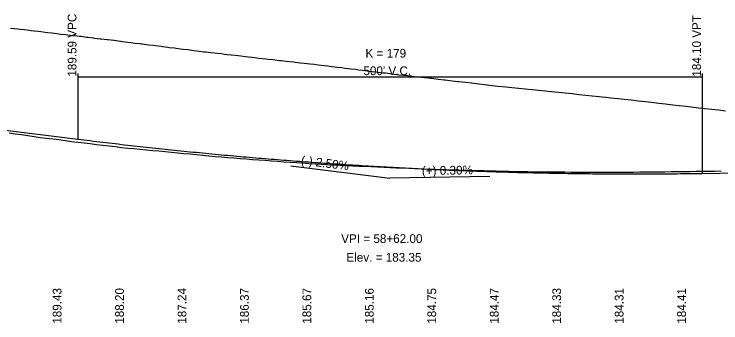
# Model space of a CAD drawing. Extents: x 1838386 to 1955906, y 719739 to 834437.
# Drawn here: x 1882224 to 1882790, y 820601 to 820848 of the extents above; entities that cross this region are included whole.
import ezdxf

# ---------------------------------------------------------------- set-up
doc = ezdxf.new("R2010")
doc.units = 0
for name, color, linetype in [('RD_DDB_GradeTX', 7, 'Continuous'), ('RD_DDB_Profile_EX', 7, 'Continuous'), ('RD_DDB_Profile_Lbl', 7, 'Continuous'), ('RD_DDB_Profile_PR', 7, 'Continuous'), ('RD_DDB_StripGrade', 7, 'Continuous'), ('RD_DDB_VCLbl', 7, 'Continuous'), ('RD_Sketch1', 7, 'Continuous')]:
    doc.layers.add(name, color=color, linetype=linetype)

msp = doc.modelspace()

# ---------------------------------------------------------------- linework, layer by layer
at = {"layer": 'RD_DDB_GradeTX'}
for p in [(1882445.7, 820726.77), (1882605.07, 820718.06)]:
    msp.add_line(p, (1882525.08, 820716.86), dxfattribs=at)
at = {"layer": 'RD_DDB_Profile_EX'}
for points in [[(1882220.15, 820753.1), (1882225.15, 820752.41), (1882230.15, 820751.66), (1882235.15, 820750.89), (1882240.15, 820750.16), (1882245.15, 820749.47), (1882250.15, 820748.87), (1882255.15, 820748.27), (1882260.15, 820747.66), (1882265.15, 820746.98), (1882270.15, 820746.26), (1882275.15, 820745.58), (1882280.15, 820745.01), (1882285.15, 820744.48), (1882290.15, 820743.84), (1882295.15, 820743.26), (1882300.15, 820742.68), (1882305.15, 820742.08), (1882310.15, 820741.45), (1882315.15, 820740.91), (1882320.15, 820740.42), (1882325.15, 820739.96), (1882330.15, 820739.51), (1882335.15, 820739.05), (1882340.15, 820738.57), (1882345.15, 820738.07), (1882350.15, 820737.58), (1882355.15, 820737.1), (1882360.15, 820736.61), (1882365.15, 820736.14), (1882370.15, 820735.7), (1882375.15, 820735.22), (1882380.15, 820734.72), (1882385.15, 820734.23), (1882390.15, 820733.82)], [(1882390.15, 820733.82), (1882395.15, 820733.43), (1882400.15, 820733), (1882405.15, 820732.56), (1882410.15, 820732.17), (1882415.15, 820731.82), (1882420.15, 820731.5), (1882425.15, 820731.14), (1882430.15, 820730.75), (1882435.15, 820730.36), (1882440.15, 820729.99), (1882445.15, 820729.64), (1882450.15, 820729.3), (1882455.15, 820728.95), (1882460.15, 820728.65), (1882465.15, 820728.33), (1882470.15, 820728.03), (1882475.15, 820727.73), (1882480.15, 820727.43), (1882485.15, 820727.12), (1882490.15, 820726.82), (1882495.15, 820726.59), (1882500.15, 820726.41), (1882505.15, 820726.27), (1882510.15, 820726.06), (1882515.15, 820725.84), (1882520.15, 820725.63), (1882525.15, 820725.38), (1882530.15, 820725.15), (1882535.15, 820724.92), (1882540.15, 820724.72), (1882545.15, 820724.53), (1882550.15, 820724.31), (1882555.15, 820724.11), (1882560.15, 820723.95), (1882565.15, 820723.8), (1882570.15, 820723.65), (1882575.15, 820723.49), (1882580.15, 820723.34), (1882585.15, 820723.18), (1882590.15, 820723.03), (1882595.15, 820722.91), (1882600.15, 820722.79), (1882605.15, 820722.68), (1882610.15, 820722.56), (1882615.15, 820722.45), (1882620.15, 820722.33), (1882625.15, 820722.23), (1882630.15, 820722.11), (1882635.15, 820721.99), (1882640.15, 820721.91), (1882645.15, 820721.88), (1882650.15, 820721.86), (1882655.15, 820721.85), (1882660.15, 820721.81), (1882665.15, 820721.74), (1882670.15, 820721.68), (1882675.15, 820721.67), (1882680.15, 820721.65), (1882685.15, 820721.63), (1882690.15, 820721.6), (1882695.15, 820721.61), (1882700.15, 820721.61), (1882705.15, 820721.62), (1882710.15, 820721.64), (1882715.15, 820721.67), (1882720.15, 820721.7), (1882725.15, 820721.72), (1882730.15, 820721.79), (1882735.15, 820721.85), (1882740.15, 820721.9), (1882745.15, 820721.97), (1882750.15, 820722.03), (1882755.15, 820722.09), (1882760.15, 820722.16), (1882765.15, 820722.23), (1882770.15, 820722.3), (1882775.15, 820722.35), (1882780.15, 820722.43), (1882785.15, 820722.51), (1882790.15, 820722.55)]]:
    msp.add_lwpolyline(points, dxfattribs=at)
at = {"layer": 'RD_DDB_Profile_PR'}
for p, q in [((1881558.08, 820837.6), (1882275.08, 820748.07)), ((1882775.08, 820720.61), (1883530.2, 820731.93))]:
    msp.add_line(p, q, dxfattribs=at)
msp.add_spline([(1882275.08, 820748.07), (1882285.08, 820746.84), (1882295.08, 820745.63), (1882305.08, 820744.45), (1882315.08, 820743.3), (1882325.08, 820742.18), (1882335.08, 820741.08), (1882345.08, 820740.02), (1882355.08, 820738.98), (1882365.08, 820737.97), (1882375.08, 820736.98), (1882385.08, 820736.03), (1882395.08, 820735.1), (1882405.08, 820734.2), (1882415.08, 820733.33), (1882425.08, 820732.49), (1882435.08, 820731.67), (1882445.08, 820730.89), (1882455.08, 820730.13), (1882465.08, 820729.4), (1882475.08, 820728.69), (1882485.08, 820728.02), (1882495.08, 820727.37), (1882505.08, 820726.75), (1882515.08, 820726.16), (1882525.08, 820725.6), (1882535.08, 820725.06), (1882545.08, 820724.55), (1882555.08, 820724.08), (1882565.08, 820723.62), (1882575.08, 820723.2), (1882585.08, 820722.8), (1882595.08, 820722.44), (1882605.08, 820722.1), (1882615.08, 820721.79), (1882625.08, 820721.5), (1882635.08, 820721.25), (1882645.08, 820721.02), (1882655.08, 820720.82), (1882665.08, 820720.65), (1882675.08, 820720.5), (1882685.08, 820720.39), (1882695.08, 820720.3), (1882705.08, 820720.24), (1882715.08, 820720.21), (1882725.08, 820720.21), (1882735.08, 820720.23), (1882745.08, 820720.28), (1882755.08, 820720.36), (1882765.08, 820720.47), (1882775.08, 820720.61)], degree=3, dxfattribs=at)
at = {"layer": 'RD_DDB_VCLbl'}
for p, q in [((1882275.08, 820800.57), (1882275.08, 820748.07)), ((1882275.08, 820798.07), (1882775.08, 820798.07)), ((1882775.08, 820800.57), (1882775.08, 820720.61))]:
    msp.add_line(p, q, dxfattribs=at)
at = {"layer": 'RD_Sketch1'}
msp.add_lwpolyline([(1882221.33, 820837), (1882224.33, 820836.68), (1882226.87, 820836.38), (1882229.17, 820836.11), (1882232.39, 820835.75), (1882234.62, 820835.51), (1882237.92, 820835.13), (1882240.2, 820834.86), (1882243.46, 820834.45), (1882245.65, 820834.16), (1882248.97, 820833.77), (1882250.92, 820833.54), (1882254.48, 820833.14), (1882256.58, 820832.9), (1882260.02, 820832.48), (1882261.71, 820832.27), (1882265.55, 820831.79), (1882267.28, 820831.57), (1882271.05, 820831.14), (1882272.4, 820830.99), (1882276.56, 820830.56), (1882277.77, 820830.44), (1882282.14, 820829.81), (1882283.18, 820829.66), (1882287.64, 820829.11), (1882288.4, 820829.01), (1882293.14, 820828.5), (1882293.86, 820828.42), (1882298.68, 820827.82), (1882299.08, 820827.77), (1882304.14, 820827.22), (1882304.21, 820827.21), (1882307.5, 820826.79), (1882309.77, 820826.43), (1882310.84, 820826.26), (1882315.25, 820825.72), (1882317.63, 820825.43), (1882320.77, 820825.05), (1882324.6, 820824.6), (1882326.29, 820824.41), (1882327, 820824.32), (1882330.19, 820823.9), (1882331.83, 820823.69), (1882335.51, 820823.21), (1882337.35, 820822.97), (1882341.83, 820822.41), (1882342.87, 820822.28), (1882347.3, 820821.72), (1882348.4, 820821.58), (1882352.5, 820821.06), (1882353.91, 820820.9), (1882357.49, 820820.48), (1882359.45, 820820.22), (1882363.24, 820819.73), (1882364.99, 820819.48), (1882368.18, 820819.02), (1882370.5, 820818.71), (1882374.12, 820818.22), (1882375.98, 820818.04), (1882377.7, 820817.87), (1882379.67, 820817.68), (1882381.51, 820817.47), (1882384.48, 820817.14), (1882387.04, 820816.86), (1882390.09, 820816.52), (1882392.57, 820816.24), (1882395, 820815.95), (1882398.09, 820815.59), (1882401.08, 820815.24), (1882403.61, 820814.95), (1882405.74, 820814.71), (1882409.15, 820814.28), (1882411.72, 820813.95), (1882414.65, 820813.63), (1882416.75, 820813.4), (1882420.17, 820813.04), (1882422.73, 820812.76), (1882425.72, 820812.4), (1882427.5, 820812.18), (1882431.24, 820811.71), (1882433.28, 820811.45), (1882436.74, 820811.1), (1882437.99, 820810.97), (1882442.28, 820810.48), (1882444.61, 820810.21), (1882447.79, 820809.87), (1882449.29, 820809.7), (1882453.32, 820809.26), (1882456.5, 820808.9), (1882458.84, 820808.65), (1882461.32, 820808.37), (1882464.38, 820807.99), (1882467.7, 820807.58), (1882469.89, 820807.32), (1882472.42, 820807.03), (1882475.43, 820806.65), (1882478.67, 820806.24), (1882480.94, 820805.97), (1882483.21, 820805.71), (1882486.46, 820805.33), (1882489.06, 820805.02), (1882491.99, 820804.68), (1882493.69, 820804.48), (1882497.53, 820803.98), (1882499.93, 820803.66), (1882503.04, 820803.28), (1882504.89, 820803.05), (1882508.58, 820802.54), (1882510.72, 820802.24), (1882514.08, 820801.86), (1882515.37, 820801.71), (1882519.59, 820801.26), (1882521.56, 820801.05), (1882525.13, 820800.62), (1882526.25, 820800.48), (1882530.67, 820799.88), (1882532.12, 820799.68), (1882536.16, 820799.25), (1882536.93, 820799.17), (1882541.69, 820798.63), (1882542.34, 820798.55), (1882546.79, 820798.04), (1882547.21, 820797.99), (1882552.74, 820797.38), (1882553.39, 820797.31), (1882557.69, 820796.89), (1882558.27, 820796.82), (1882563.79, 820796.16), (1882563.85, 820796.16), (1882568.45, 820795.63), (1882569.32, 820795.53), (1882574.84, 820794.87), (1882574.92, 820794.86), (1882579.75, 820794.3), (1882580.35, 820794.23), (1882585.81, 820793.61), (1882585.87, 820793.61), (1882590.36, 820793.13), (1882596.29, 820792.37), (1882600.82, 820791.86), (1882607, 820791.11), (1882611.79, 820790.54), (1882617.81, 820789.95), (1882622.75, 820789.43), (1882628.36, 820788.83), (1882633.31, 820788.27), (1882638.98, 820787.73), (1882643.86, 820787.27), (1882649.58, 820786.68), (1882654.27, 820786.2), (1882660.16, 820785.55), (1882665.25, 820785.04), (1882671.11, 820784.49), (1882676.43, 820783.93), (1882681.91, 820783.37), (1882686.9, 820782.81), (1882692.54, 820782.12), (1882695.07, 820781.85), (1882697.85, 820781.55), (1882701.98, 820781.16), (1882707.53, 820780.68), (1882712.97, 820780.14), (1882718.41, 820779.48), (1882723.95, 820778.75), (1882729.76, 820778.09), (1882734.62, 820777.56), (1882740.3, 820776.91), (1882745.71, 820776.27), (1882751.57, 820775.63), (1882756.71, 820775.1), (1882762.29, 820774.45), (1882766.28, 820773.94), (1882772.16, 820773.21), (1882777.13, 820772.63), (1882782.76, 820772), (1882788.01, 820771.43), (1882793.77, 820770.7)], dxfattribs=at)
msp.add_lwpolyline([(1882221.33, 820837), (1882224.33, 820836.68), (1882226.87, 820836.38), (1882229.17, 820836.11), (1882232.39, 820835.75), (1882234.62, 820835.51), (1882237.92, 820835.13), (1882240.2, 820834.86), (1882243.46, 820834.45), (1882245.65, 820834.16), (1882248.97, 820833.77), (1882250.92, 820833.54), (1882254.48, 820833.14), (1882256.58, 820832.9), (1882260.02, 820832.48), (1882261.71, 820832.27), (1882265.55, 820831.79), (1882267.28, 820831.57), (1882271.05, 820831.14), (1882272.4, 820830.99), (1882276.56, 820830.56), (1882277.77, 820830.44), (1882282.14, 820829.81), (1882283.18, 820829.66), (1882287.64, 820829.11), (1882288.4, 820829.01), (1882293.14, 820828.5), (1882293.86, 820828.42), (1882298.68, 820827.82), (1882299.08, 820827.77), (1882304.14, 820827.22), (1882304.21, 820827.21), (1882307.5, 820826.79), (1882309.77, 820826.43), (1882310.84, 820826.26), (1882315.25, 820825.72), (1882317.63, 820825.43), (1882320.77, 820825.05), (1882324.6, 820824.6), (1882326.29, 820824.41), (1882327, 820824.32), (1882330.19, 820823.9), (1882331.83, 820823.69), (1882335.51, 820823.21), (1882337.35, 820822.97), (1882341.83, 820822.41), (1882342.87, 820822.28), (1882347.3, 820821.72), (1882348.4, 820821.58), (1882352.5, 820821.06), (1882353.91, 820820.9), (1882357.49, 820820.48), (1882359.45, 820820.22), (1882363.24, 820819.73), (1882364.99, 820819.48), (1882368.18, 820819.02), (1882370.5, 820818.71), (1882374.12, 820818.22), (1882375.98, 820818.04), (1882377.7, 820817.87), (1882379.67, 820817.68), (1882381.51, 820817.47), (1882384.48, 820817.14), (1882387.04, 820816.86), (1882390.09, 820816.52), (1882392.57, 820816.24), (1882395, 820815.95), (1882398.09, 820815.59), (1882401.08, 820815.24), (1882403.61, 820814.95), (1882405.74, 820814.71), (1882409.15, 820814.28), (1882411.72, 820813.95), (1882414.65, 820813.63), (1882416.75, 820813.4), (1882420.17, 820813.04), (1882422.73, 820812.76), (1882425.72, 820812.4), (1882427.5, 820812.18), (1882431.24, 820811.71), (1882433.28, 820811.45), (1882436.74, 820811.1), (1882437.99, 820810.97), (1882442.28, 820810.48), (1882444.61, 820810.21), (1882447.79, 820809.87), (1882449.29, 820809.7), (1882453.32, 820809.26), (1882456.5, 820808.9), (1882458.84, 820808.65), (1882461.32, 820808.37), (1882464.38, 820807.99), (1882467.7, 820807.58), (1882469.89, 820807.32), (1882472.42, 820807.03), (1882475.43, 820806.65), (1882478.67, 820806.24), (1882480.94, 820805.97), (1882483.21, 820805.71), (1882486.46, 820805.33), (1882489.06, 820805.02), (1882491.99, 820804.68), (1882493.69, 820804.48), (1882497.53, 820803.98), (1882499.93, 820803.66), (1882503.04, 820803.28), (1882504.89, 820803.05), (1882508.58, 820802.54), (1882510.72, 820802.24), (1882514.08, 820801.86), (1882515.37, 820801.71), (1882519.59, 820801.26), (1882521.56, 820801.05), (1882525.13, 820800.62), (1882526.25, 820800.48), (1882530.67, 820799.88), (1882532.12, 820799.68), (1882536.16, 820799.25), (1882536.93, 820799.17), (1882541.69, 820798.63), (1882542.34, 820798.55), (1882546.79, 820798.04), (1882547.21, 820797.99), (1882552.74, 820797.38), (1882553.39, 820797.31), (1882557.69, 820796.89), (1882558.27, 820796.82), (1882563.79, 820796.16), (1882563.85, 820796.16), (1882568.45, 820795.63), (1882569.32, 820795.53), (1882574.84, 820794.87), (1882574.92, 820794.86), (1882579.75, 820794.3), (1882580.35, 820794.23), (1882585.81, 820793.61), (1882585.87, 820793.61), (1882590.36, 820793.13), (1882596.29, 820792.37), (1882600.82, 820791.86), (1882607, 820791.11), (1882611.79, 820790.54), (1882617.81, 820789.95), (1882622.75, 820789.43), (1882628.36, 820788.83), (1882633.31, 820788.27), (1882638.98, 820787.73), (1882643.86, 820787.27), (1882649.58, 820786.68), (1882654.27, 820786.2), (1882660.16, 820785.55), (1882665.25, 820785.04), (1882671.11, 820784.49), (1882676.43, 820783.93), (1882681.91, 820783.37), (1882686.9, 820782.81), (1882692.54, 820782.12), (1882695.07, 820781.85), (1882697.85, 820781.55), (1882701.98, 820781.16), (1882707.53, 820780.68), (1882712.97, 820780.14), (1882718.41, 820779.48), (1882723.95, 820778.75), (1882729.76, 820778.09), (1882734.62, 820777.56), (1882740.3, 820776.91), (1882745.71, 820776.27), (1882751.57, 820775.63), (1882756.71, 820775.1), (1882762.29, 820774.45), (1882766.28, 820773.94), (1882772.16, 820773.21), (1882777.13, 820772.63), (1882782.76, 820772), (1882788.01, 820771.43), (1882793.77, 820770.7)], dxfattribs=at)
msp.add_lwpolyline([(1882221.33, 820837), (1882224.33, 820836.68), (1882226.87, 820836.38), (1882229.17, 820836.11), (1882232.39, 820835.75), (1882234.62, 820835.51), (1882237.92, 820835.13), (1882240.2, 820834.86), (1882243.46, 820834.45), (1882245.65, 820834.16), (1882248.97, 820833.77), (1882250.92, 820833.54), (1882254.48, 820833.14), (1882256.58, 820832.9), (1882260.02, 820832.48), (1882261.71, 820832.27), (1882265.55, 820831.79), (1882267.28, 820831.57), (1882271.05, 820831.14), (1882272.4, 820830.99), (1882276.56, 820830.56), (1882277.77, 820830.44), (1882282.14, 820829.81), (1882283.18, 820829.66), (1882287.64, 820829.11), (1882288.4, 820829.01), (1882293.14, 820828.5), (1882293.86, 820828.42), (1882298.68, 820827.82), (1882299.08, 820827.77), (1882304.14, 820827.22), (1882304.21, 820827.21), (1882307.5, 820826.79), (1882309.77, 820826.43), (1882310.84, 820826.26), (1882315.25, 820825.72), (1882317.63, 820825.43), (1882320.77, 820825.05), (1882324.6, 820824.6), (1882326.29, 820824.41), (1882327, 820824.32), (1882330.19, 820823.9), (1882331.83, 820823.69), (1882335.51, 820823.21), (1882337.35, 820822.97), (1882341.83, 820822.41), (1882342.87, 820822.28), (1882347.3, 820821.72), (1882348.4, 820821.58), (1882352.5, 820821.06), (1882353.91, 820820.9), (1882357.49, 820820.48), (1882359.45, 820820.22), (1882363.24, 820819.73), (1882364.99, 820819.48), (1882368.18, 820819.02), (1882370.5, 820818.71), (1882374.12, 820818.22), (1882375.98, 820818.04), (1882377.7, 820817.87), (1882379.67, 820817.68), (1882381.51, 820817.47), (1882384.48, 820817.14), (1882387.04, 820816.86), (1882390.09, 820816.52), (1882392.57, 820816.24), (1882395, 820815.95), (1882398.09, 820815.59), (1882401.08, 820815.24), (1882403.61, 820814.95), (1882405.74, 820814.71), (1882409.15, 820814.28), (1882411.72, 820813.95), (1882414.65, 820813.63), (1882416.75, 820813.4), (1882420.17, 820813.04), (1882422.73, 820812.76), (1882425.72, 820812.4), (1882427.5, 820812.18), (1882431.24, 820811.71), (1882433.28, 820811.45), (1882436.74, 820811.1), (1882437.99, 820810.97), (1882442.28, 820810.48), (1882444.61, 820810.21), (1882447.79, 820809.87), (1882449.29, 820809.7), (1882453.32, 820809.26), (1882456.5, 820808.9), (1882458.84, 820808.65), (1882461.32, 820808.37), (1882464.38, 820807.99), (1882467.7, 820807.58), (1882469.89, 820807.32), (1882472.42, 820807.03), (1882475.43, 820806.65), (1882478.67, 820806.24), (1882480.94, 820805.97), (1882483.21, 820805.71), (1882486.46, 820805.33), (1882489.06, 820805.02), (1882491.99, 820804.68), (1882493.69, 820804.48), (1882497.53, 820803.98), (1882499.93, 820803.66), (1882503.04, 820803.28), (1882504.89, 820803.05), (1882508.58, 820802.54), (1882510.72, 820802.24), (1882514.08, 820801.86), (1882515.37, 820801.71), (1882519.59, 820801.26), (1882521.56, 820801.05), (1882525.13, 820800.62), (1882526.25, 820800.48), (1882530.67, 820799.88), (1882532.12, 820799.68), (1882536.16, 820799.25), (1882536.93, 820799.17), (1882541.69, 820798.63), (1882542.34, 820798.55), (1882546.79, 820798.04), (1882547.21, 820797.99), (1882552.74, 820797.38), (1882553.39, 820797.31), (1882557.69, 820796.89), (1882558.27, 820796.82), (1882563.79, 820796.16), (1882563.85, 820796.16), (1882568.45, 820795.63), (1882569.32, 820795.53), (1882574.84, 820794.87), (1882574.92, 820794.86), (1882579.75, 820794.3), (1882580.35, 820794.23), (1882585.81, 820793.61), (1882585.87, 820793.61), (1882590.36, 820793.13), (1882596.29, 820792.37), (1882600.82, 820791.86), (1882607, 820791.11), (1882611.79, 820790.54), (1882617.81, 820789.95), (1882622.75, 820789.43), (1882628.36, 820788.83), (1882633.31, 820788.27), (1882638.98, 820787.73), (1882643.86, 820787.27), (1882649.58, 820786.68), (1882654.27, 820786.2), (1882660.16, 820785.55), (1882665.25, 820785.04), (1882671.11, 820784.49), (1882676.43, 820783.93), (1882681.91, 820783.37), (1882686.9, 820782.81), (1882692.54, 820782.12), (1882695.07, 820781.85), (1882697.85, 820781.55), (1882701.98, 820781.16), (1882707.53, 820780.68), (1882712.97, 820780.14), (1882718.41, 820779.48), (1882723.95, 820778.75), (1882729.76, 820778.09), (1882734.62, 820777.56), (1882740.3, 820776.91), (1882745.71, 820776.27), (1882751.57, 820775.63), (1882756.71, 820775.1), (1882762.29, 820774.45), (1882766.28, 820773.94), (1882772.16, 820773.21), (1882777.13, 820772.63), (1882782.76, 820772), (1882788.01, 820771.43), (1882793.77, 820770.7)], dxfattribs=at)

# ---------------------------------------------------------------- texts
at = {"layer": 'RD_DDB_GradeTX'}
for s, rotation, p in [('(-) 2.50%', 352.8826, (1882453.57, 820727.8)), ('(+) 0.30%', 0.8594, (1882550.72, 820719.24))]:
    msp.add_text(s, height=7, rotation=rotation, dxfattribs=at).set_placement(p)
at = {"layer": 'RD_DDB_Profile_Lbl'}
for s, p in [('VPI = 58+62.00', (1882486.06, 820664.86)), ('Elev. = 183.35', (1882490.22, 820649.86))]:
    msp.add_text(s, height=7, dxfattribs=at).set_placement(p)
at = {"layer": 'RD_DDB_StripGrade'}
for s, p in [('189.59 VPC', (1882274.08, 820798.07)), ('184.10 VPT', (1882774.08, 820798.07)), ('189.43', (1882262.08, 820600.13)), ('188.20', (1882312.08, 820600.13)), ('187.24', (1882362.08, 820600.13)), ('186.37', (1882412.08, 820600.13)), ('185.67', (1882462.08, 820600.13)), ('185.16', (1882512.08, 820600.13)), ('184.75', (1882562.08, 820600.13)), ('184.47', (1882612.08, 820600.13)), ('184.33', (1882662.08, 820600.13)), ('184.31', (1882712.08, 820600.13)), ('184.41', (1882762.08, 820600.13))]:
    msp.add_text(s, height=7, rotation=90, dxfattribs=at).set_placement(p)
at = {"layer": 'RD_DDB_VCLbl'}
for s, p in [('K = 179', (1882505.52, 820813.32)), ("500' V.C.", (1882503.83, 820799.32))]:
    msp.add_text(s, height=7, dxfattribs=at).set_placement(p)

doc.saveas('drawing.dxf')
